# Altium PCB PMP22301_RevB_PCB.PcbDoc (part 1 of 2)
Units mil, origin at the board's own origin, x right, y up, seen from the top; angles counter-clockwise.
Board outline 2805 x 3100 mil, 4 copper layers (Top Layer, Signal Layer 1, Signal Layer 2, Bottom Layer), stack 61.2 mil thick; 104 components, 74 nets, 288 pads, 112 vias.
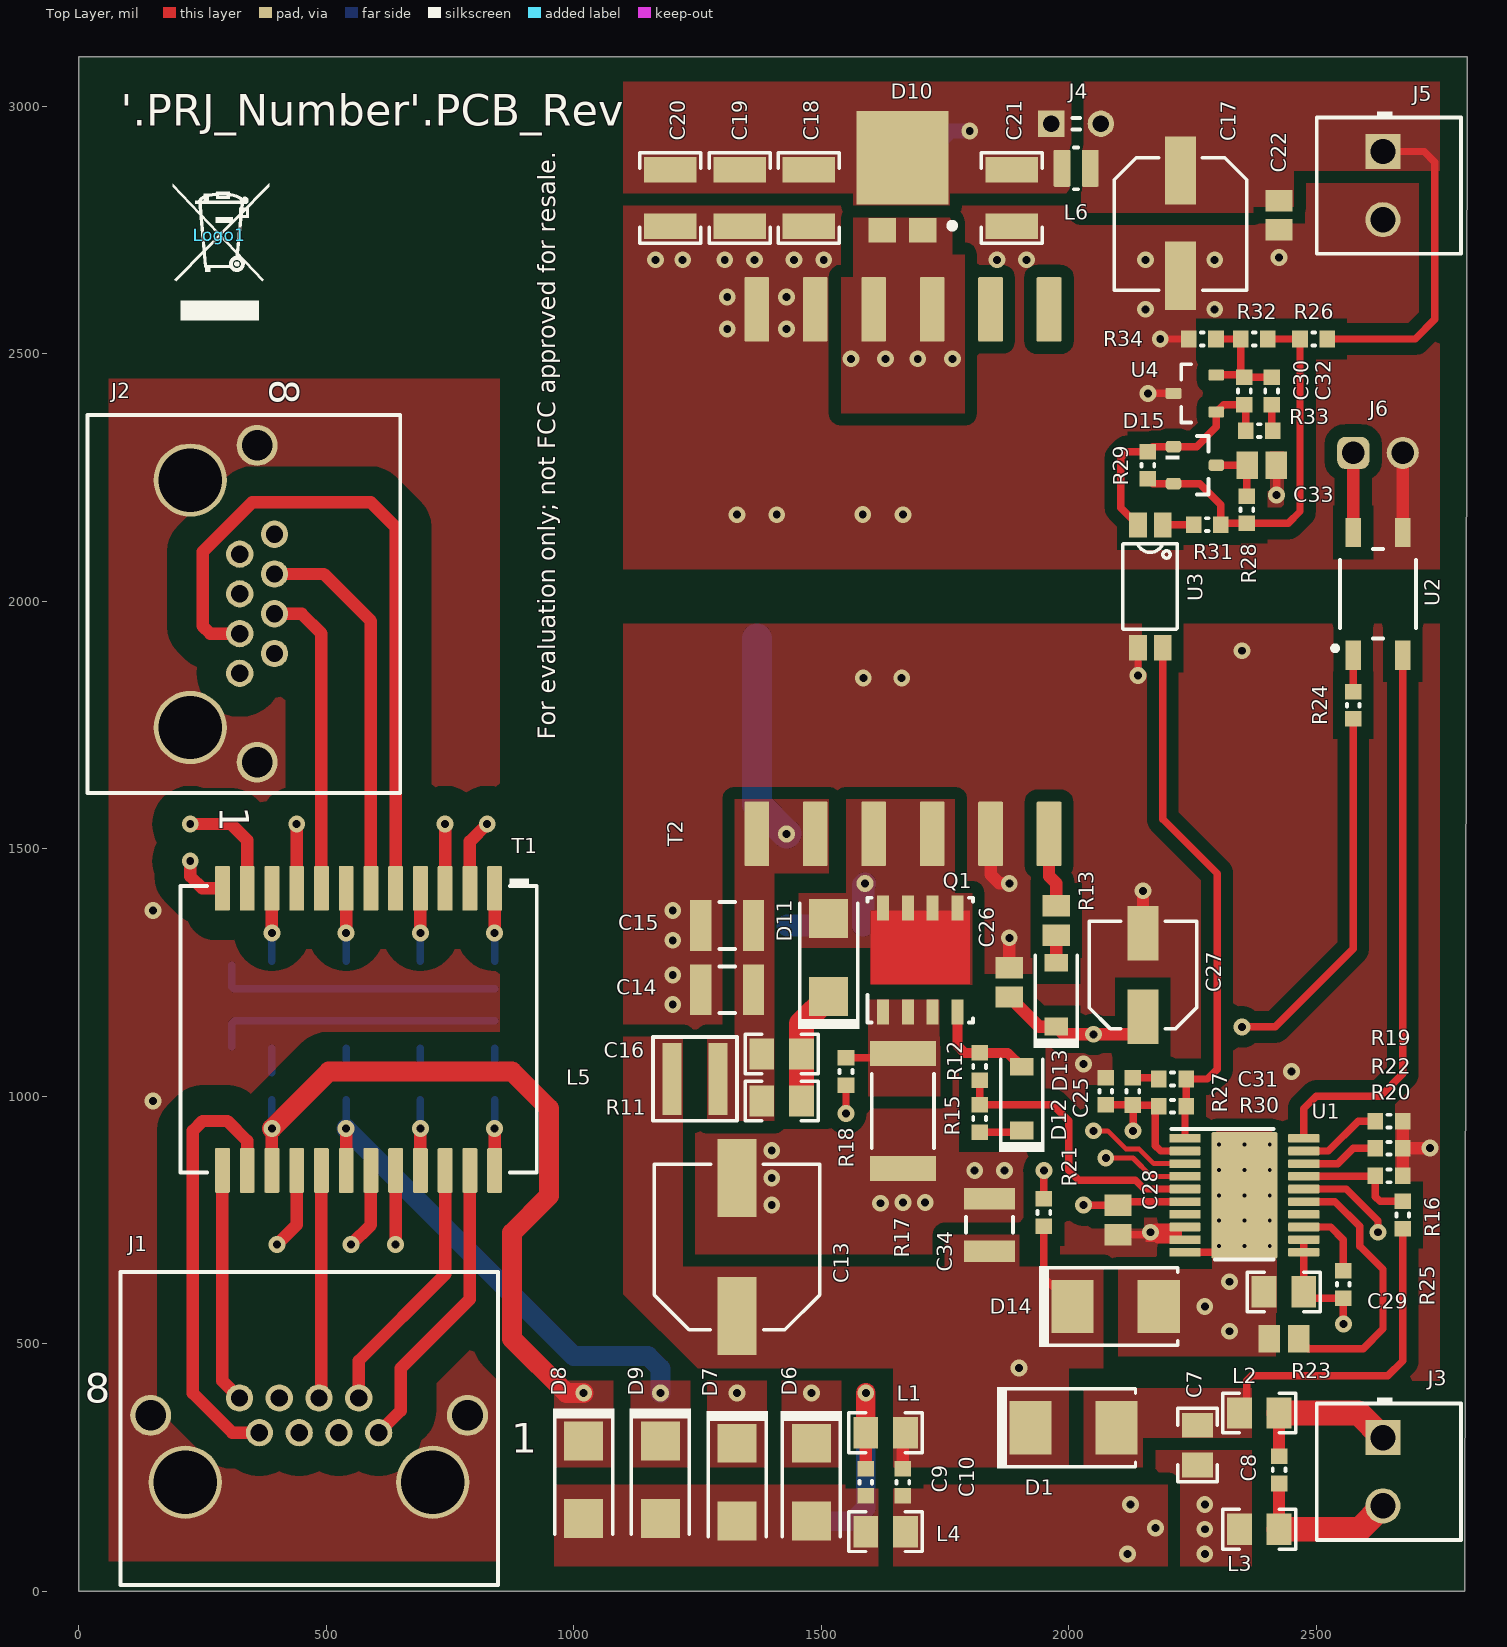
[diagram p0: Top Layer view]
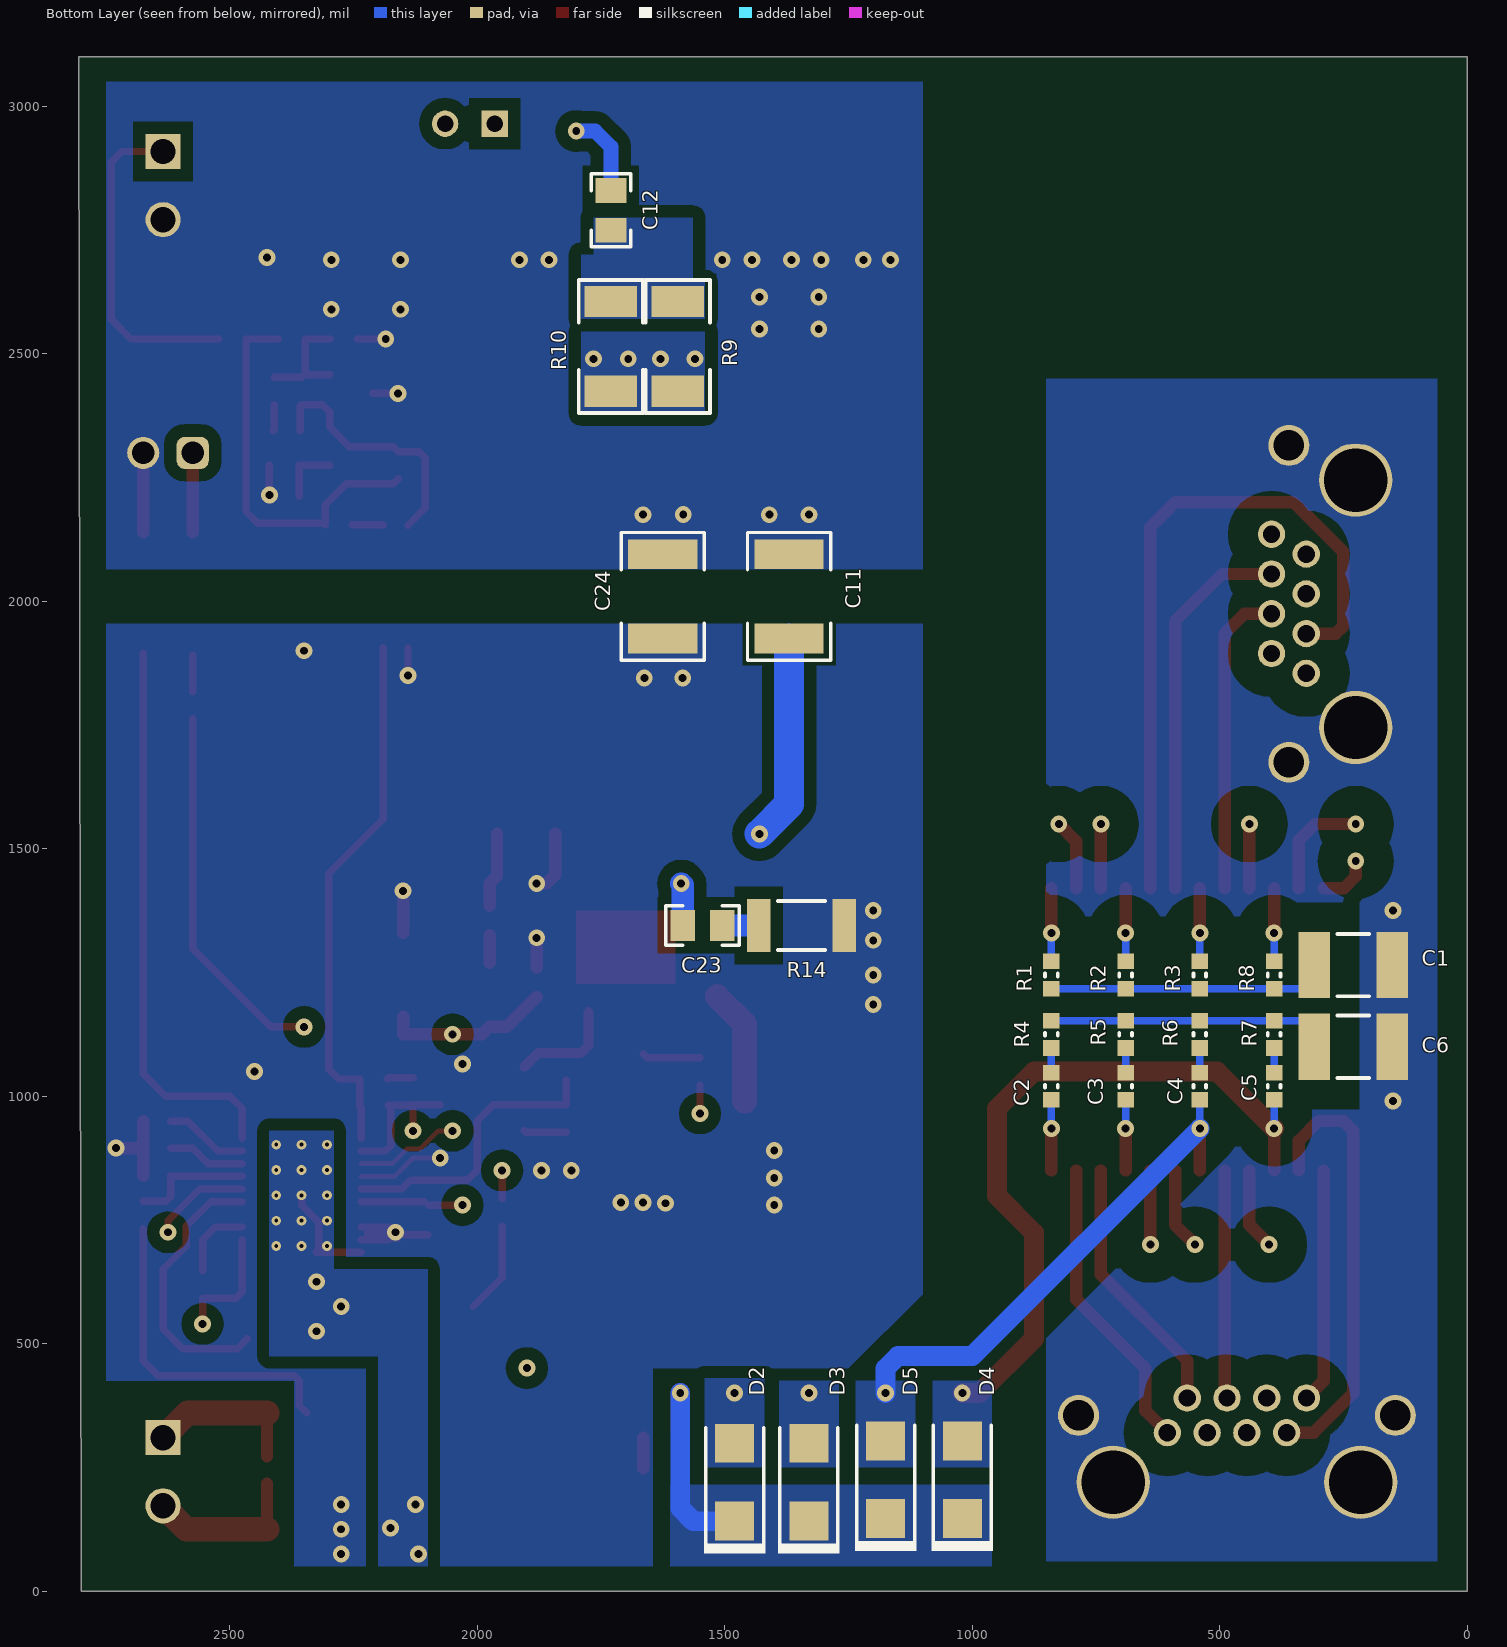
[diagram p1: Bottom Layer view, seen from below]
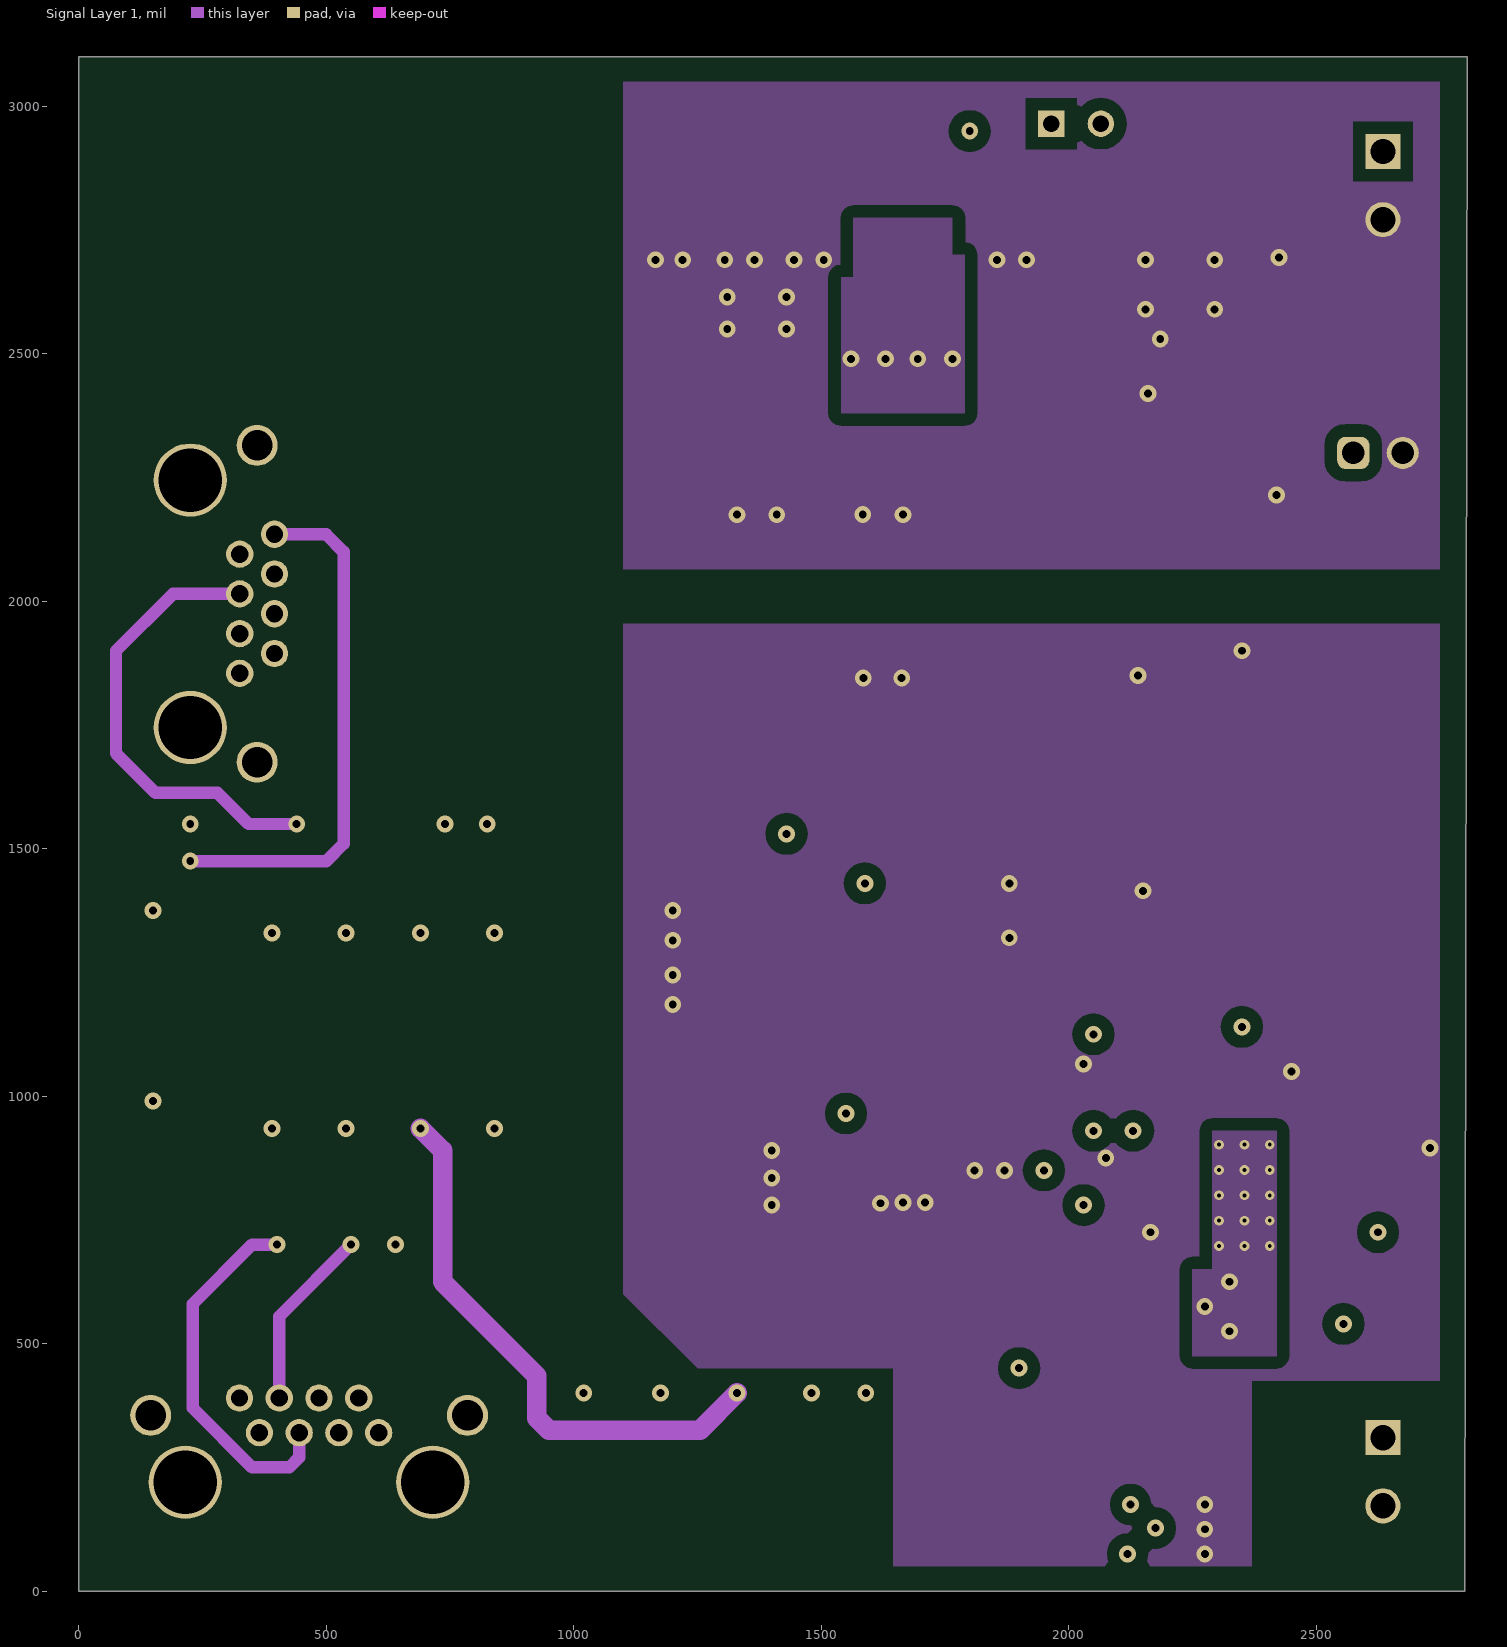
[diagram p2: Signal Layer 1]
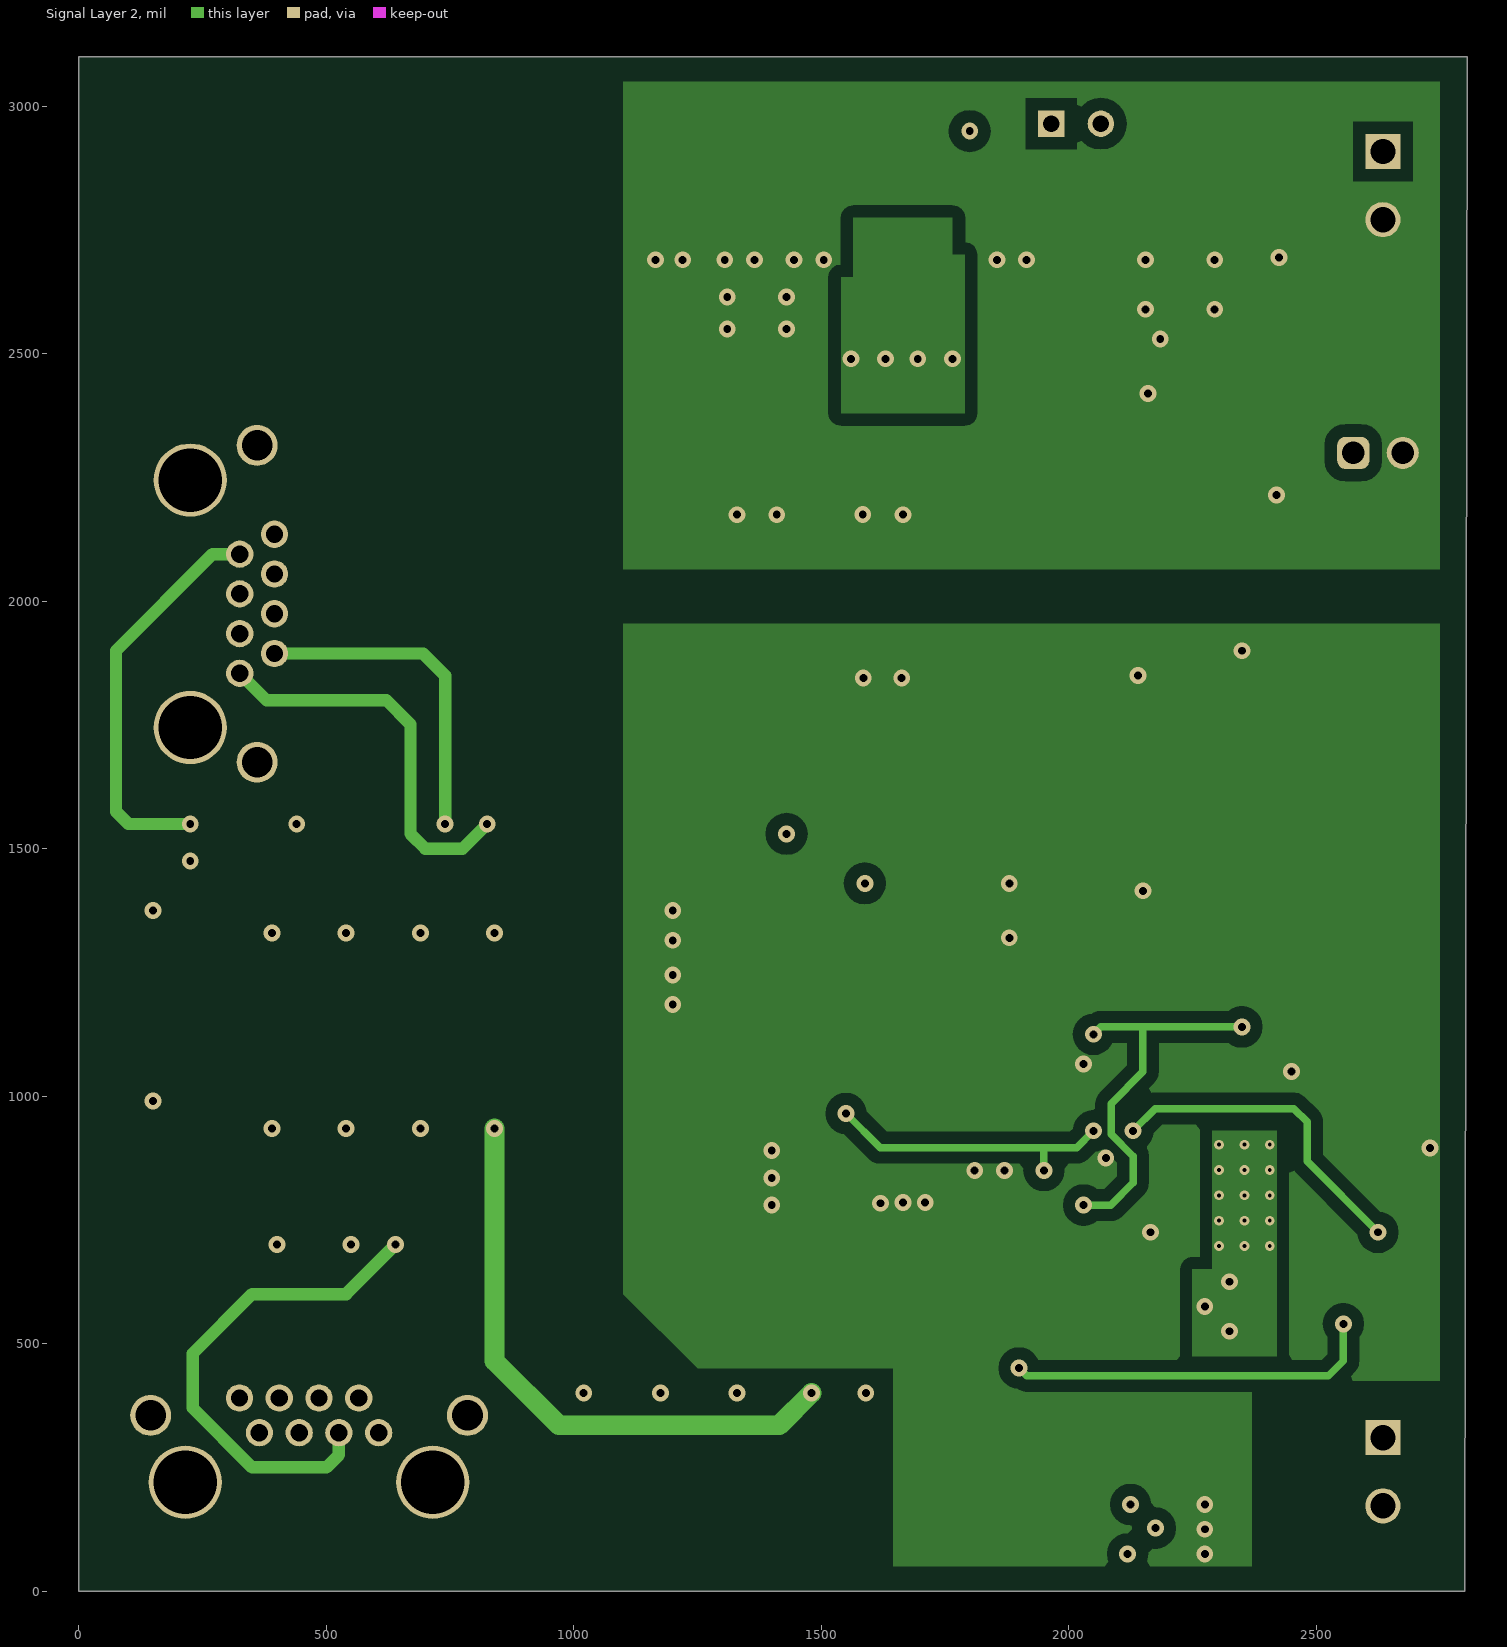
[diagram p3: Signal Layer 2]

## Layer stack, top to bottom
Top Solder: solder mask 0.4, Solder Resist, Dk 3.5
Top Layer: signal copper 2.8
Dielectric 2: core 15, Dk 4.2
Signal Layer 1: signal copper 2.8
Dielectric 3: prepreg 20, Dk 4.2
Signal Layer 2: signal copper 2.8
Dielectric1: core 15, FR-4, Dk 4.8
Bottom Layer: signal copper 2.8
Bottom Solder: solder mask 0.4, Solder Resist, Dk 3.5

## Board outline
0,0 2800,0 2805,3100 0,3100

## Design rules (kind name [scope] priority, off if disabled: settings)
AcuteAngle [All] p1: minimum=4.50000000000000E+0001 checktracksonly=FALSE
AssemblyTestPointUsage [All] p1: valid=2
BoardOutlineClearance BoardOutlineClearance_MountingHoles [OnCopper and InComponentClass('Mounting Holes')] p1: gap=39.37 ignorepadtopadclearanceinfootprint=FALSE
BoardOutlineClearance BoardOutlineClearance_Poly [OnCopper and IsPoly] p2: gap=25 ignorepadtopadclearanceinfootprint=FALSE
BoardOutlineClearance [OnCopper and Not InComponentClass('Logo') and not InComponentClass('FiducialMark') and not InRegion(1000,500,4000,800) and not InPoly] p3: gap=50 ignorepadtopadclearanceinfootprint=FALSE
Clearance Clearance_2 [InNamedPolygon('TOP_LAYER_BSP_P114')] p1: gap=60 ignorepadtopadclearanceinfootprint=FALSE
Clearance Clearance_1 [InNamedPolygon('BOTTOM_LAYER_BSP_P116')] p2: gap=60 ignorepadtopadclearanceinfootprint=FALSE
Clearance Clearance_Keepouts [((IsTrack Or IsArc) And Not InPoly) And IsFree and IsKeepOut vs ((IsTrack Or IsArc) And Not InPoly) And IsFree and IsKeepOut] p3: gap=0 ignorepadtopadclearanceinfootprint=FALSE
Clearance Clearance_Poly [InPolygon] p4: gap=25 ignorepadtopadclearanceinfootprint=TRUE
Clearance Clearance_FiducialMark [IsKeepOut and InComponentClass('FiducialMark') vs IsPad and InComponentClass('FiducialMark')] p5: gap=0 ignorepadtopadclearanceinfootprint=FALSE
Clearance [All] p6: gap=7.87 ignorepadtopadclearanceinfootprint=TRUE
ComponentClearance ComponentClearance_MountingHoles_FiducialMarks [InComponentClass('Mounting Holes') vs InComponentClass('FiducialMark')] p1: gap=50 collisioncheckmode=3 verticalgap=10 showdistances=FALSE
ComponentClearance ComponentClearance_Shunt [InComponentClass('Header') vs InComponentClass('Shunt')] p2: gap=0 collisioncheckmode=3 verticalgap=0 showdistances=FALSE
ComponentClearance ComponentClearance_Logo [InComponentClass('Logo')] p3: gap=50 collisioncheckmode=3 verticalgap=10 showdistances=FALSE
ComponentClearance ComponentClearance_ScrewToNut [(HasFootprint('NY PMS 440 0025 PH')) vs (HasFootprint('Keystone_1902C'))] p4: gap=5 collisioncheckmode=3 verticalgap=10 showdistances=FALSE
ComponentClearance ComponentClearance_MountingHoles [InComponentClass('Mounting Holes')] p5: gap=250 collisioncheckmode=3 verticalgap=100000 showdistances=FALSE
ComponentClearance ComponentClearance_SmallPassives [HasFootprint('0201*') or HasFootprint('0402*') or HasFootprint('0508') or HasFootprint('0603*') or HasFootprint('0612') or HasFootprint('0805*') or HasFootprint('0815*') or HasFootprint('0830*') or HasFootprint('1206*') or HasFootprint('1210*') or HasFootprint('1808*') or HasFootprint('1812*') or HasFootprint('1825*') or HasFootprint('2010*') or HasFootprint('2220*') or HasFootprint('2225*') or HasFootprint('2512*') or HasFootprint('2728*') or HasFootprint('3518*') vs HasFootprint('0201*') or HasFootprint('0402*') or HasFootprint('0508') or HasFootprint('0603*') or HasFootprint('0612') or HasFootprint('0805*') or HasFootprint('0815*') or HasFootprint('0830*') or HasFootprint('1206*') or HasFootprint('1210*') or HasFootprint('1808*') or HasFootprint('1812*') or HasFootprint('1825*') or HasFootprint('2010*') or HasFootprint('2220*') or HasFootprint('2225*') or HasFootprint('2512*') or HasFootprint('2728*') or HasFootprint('3518*')] p6: gap=14.96 collisioncheckmode=3 verticalgap=10 showdistances=FALSE
ComponentClearance ComponentClearance_THtoSMT [IsThruComponent vs IsSMTComponent] p7: gap=40 collisioncheckmode=3 verticalgap=30 showdistances=FALSE
ComponentClearance ComponentClearance_THtoTH [IsThruComponent vs IsThruComponent] p8: gap=30 collisioncheckmode=3 verticalgap=30 showdistances=FALSE
ComponentClearance [All] p9: gap=30 collisioncheckmode=3 verticalgap=10 showdistances=FALSE
DiffPairsRouting [All] p1: maxlimit=100 minlimit=10 mostfreqgap=10 toplayer_minwidth=15 toplayer_maxwidth=15 toplayer_prefwidth=15 midlayer1_minwidth=15 midlayer1_maxwidth=15 midlayer1_prefwidth=15 midlayer2_minwidth=15 midlayer2_maxwidth=15 midlayer2_prefwidth=15 bottomlayer_minwidth=15 bottomlayer_maxwidth=15 bottomlayer_prefwidth=15 maxuncoupledlength=1000
FabricationTestPointUsage TestPointUsage [All] p1: valid=2 allowmultiple=FALSE
FabricationTestpoint Testpoint [All] p1: side=3 testpointundercomponent=TRUE minsize=40 maxsize=100 preferedsize=60 minholesize=0 maxholesize=40 preferedholesize=32 testpointgrid=1 allowsidetop=TRUE allowsidebottom=TRUE usegrid=TRUE gridtolerance=0.01
FanoutControl Fanout_LCC [IsLCC] p1: bgadir=Out bgaviamode=Centered fanoutstyle=Auto fanoutdirection=Alternating viagrid=1 // Fanout_LCC (Default Rule)
FanoutControl Fanout_BGA [IsBGA] p2: bgadir=Out bgaviamode=Centered fanoutstyle=Auto fanoutdirection=Alternating viagrid=1 // Fanout_BGA (Default Rule)
FanoutControl Fanout_Default [All] p4: bgadir=Out bgaviamode=Centered fanoutstyle=Auto fanoutdirection=Alternating viagrid=1 // Fanout_Default (Default Rule)
FanoutControl Fanout_Small [(CompPinCount < 5)] p5: bgadir=Out bgaviamode=Centered fanoutstyle=Auto fanoutdirection=OutThenIn viagrid=1 // Fanout_Small (Default Rule)
HoleSize [All] p1: absolutevalues=TRUE maxlimit=251 minlimit=7.87 maxpercent=80.000 minpercent=20.000
MinimumAnnularRing MinimumAnnularRing_ThermalPadVias [IsVia and InAnyComponent] p1: minimumring=5.91
MinimumAnnularRing [All] p2: minimumring=7.87
MinimumSolderMaskSliver MinimumSolderMaskSliver_Logo [InComponentClass('Logo') vs InComponentClass('Logo')] p1: minsoldermaskwidth=0.7
MinimumSolderMaskSliver [All] p2: minsoldermaskwidth=3.94
PlaneConnect [All] p1: planeconnectstyle=Relief reliefexpansion=10 reliefentries=4 reliefconductorwidth=10 reliefairgap=10
PolygonConnect [All] p1: connectstyle=Direct reliefconductorwidth=10 reliefentries=4 polygonreliefangle="90 Angle" airgapwidth=10
RoutingVias ThermalPadVias [IsVia and InAnyComponent] p1: holewidth=7.87 width=19.68 viastyle="Through Hole" minholewidth=7.87 minwidth=19.68 maxholewidth=12.99 maxwidth=23.62
RoutingVias [All] p2: holewidth=16 width=34 viastyle="Through Hole" minholewidth=7.87 minwidth=26 maxholewidth=40 maxwidth=65
SilkToBoardRegionClearance [Not ((IsComment or IsDesignator) And (Hide <> 'False')) and not InRegion(1000,500,4000,800)] p1:
SilkToSilkClearance SilkToSilkClearance_Pb-FreeLogo [(HasFootprint('Pb-Free_Overlay_Medium') OR HasFootprint('Pb-Free_Overlay_Small')) vs (HasFootprint('Pb-Free_Overlay_Medium') OR HasFootprint('Pb-Free_Overlay_Small'))] p1: silktosilkclearance=0
SilkToSilkClearance [All] p2: silktosilkclearance=3.94
SilkToSolderMaskClearance SilkToComponentPadClearance [(IsPad or IsFill or IsRegion) and InAnycomponent] p1: minsilkscreentomaskgap=5 clearancetoexposedcopper=TRUE
SilkToSolderMaskClearance "Silk to Solder Mask Opening" [All] p2: minsilkscreentomaskgap=3.94 clearancetoexposedcopper=FALSE
SolderMaskExpansion [All] p1: expansion=1.97
UnRoutedNet [All] p1: checkbadconnections=TRUE
Width [All] p1: maxlimit=100 minlimit=6 preferedwidth=10 checkconnectedcopper=TRUE
14 further rules are at their usual default settings.

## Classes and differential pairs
component class PMP22301_RevB_SH2: C11 C12 C13 C14 C15 C16 C17 C18 C19 C20 C21 C22 C23 C24 C25 C26 C27 C28 C29 C30 C31 C32 C33 C34 D10 D11 D12 D13 D14 D15 J4 J5 J6 L5 L6 Q1 R9 R10 R11 R12 R13 R14 R15 R16 R17 R18 R19 R20 R21 R22 R23 R24 R25 R26 R27 R28 R29 R30 R31 R32 R33 R34 T2 U1 U2 U3 U4
component class PMP22301_RevB_SH1: C1 C2 C3 C4 C5 C6 C7 C8 C9 C10 D1 D2 D3 D4 D5 D6 D7 D8 D9 J1 J2 J3 L1 L2 L3 L4 Logo1 Logo2 R1 R2 R3 R4 R5 R6 R7 R8 T1
component class Header: J6

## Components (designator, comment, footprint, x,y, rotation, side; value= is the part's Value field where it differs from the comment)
C1 "GR443QR73D102KW01L" 1812 230,1265 r0 bottom value=1000pF
C2 "885012206114" 0603L 840,1020 r270 bottom value=0.01uF
C3 "885012206114" 0603L 690,1020 r270 bottom value=0.01uF
C4 "885012206114" 0603L 540,1020 r270 bottom value=0.01uF
C5 "885012206114" 0603L 390,1020 r270 bottom value=0.01uF
C6 "GR443QR73D102KW01L" 1812 230,1100 r180 bottom value=1000pF
C7 "885012207128" 0805_HV 2260,295 r90 top value=0.1uF
C8 "Capacitor" 0603L 2425,245 r270 top value=1000pF
C9 "Capacitor" 0603L 1590,220 r270 top value=1000pF
C10 "Capacitor" 0603L 1665,220 r270 top value=1000pF
C11 "Capacitor" 1812_HV 1370,2010 r270 bottom value=2200pF
C12 "GRM21A5C2E331JW01D" 0805_HV 1730,2790 r270 bottom value=330pF
C13 "Cap_Polarized" SM_RADIAL_F 1329.65,695.24 r90 top value=47uF
C14 "Capacitor" 1210_270L 1310,1215 r180 top value=2.2uF
C15 "Capacitor" 1210_270L 1310,1345 r180 top value=2.2uF
C16 "885012207128" 0805_HV 1420,1085 r180 top value=0.1uF
C17 "35SVPF22M" CAPSMT_62_F61 2225,2765 r270 top value=22uF
C18 "GRM32ER71H475KA88L" 1210_270 1475,2815 r90 top value=4.7uF
C19 "GRM32ER71H475KA88L" 1210_270 1335,2815 r90 top value=4.7uF
C20 "GRM32ER71H475KA88L" 1210_270 1195,2815 r90 top value=4.7uF
C21 "GRM32ER71H475KA88L" 1210_270 1885,2815 r90 top value=4.7uF
C22 "885012207103" 0805L 2425,2780 r270 top value=1uF
C23 "Capacitor" 0805_HV 1545,1345 r180 bottom value=100pF
C24 "Capacitor" 1812_HV 1625,2010 r270 bottom value=2200pF
C25 "Capacitor" 0603L 2075,1010 r270 top value=0.1uF
C26 "885012207103" 0805L 1880,1230 r90 top value=1uF
C27 "Cap_Polarized" SM_RADIAL_C 2150,1245 r90 top value=22uF
C28 "885012207103" 0805L 2099.69,749.68 r270 top value=1uF
C29 "885012207128" 0805_HV 2434.69,604.68 r0 top value=0.1uF
C30 "Capacitor" 0603L 2355,2425 r270 top value=100pF
C31 "GRM188R71E473KA01D" 0603L 2209.69,1034.68 r180 top value=0.047uF
C32 "GRM188R71E273KA01D" 0603L 2410,2425 r270 top value=0.027uF
C33 "885012207103" 0805L 2390,2275 r0 top value=1uF
C34 "Capacitor" 1210_270L 1840,740 r90 top value=2.2uF
D1 "B2100-13-F" SMB 2010,330 r0 top value=100V
D2 "B1100-13-F" SMA 1480,220 r90 bottom value=100V
D3 "B1100-13-F" SMA 1330,220 r90 bottom value=100V
D4 "B1100-13-F" SMA 1020,225 r90 bottom value=100V
D5 "B1100-13-F" SMA 1175,225 r90 bottom value=100V
D6 "B1100-13-F" SMA 1480,220 r270 top value=100V
D7 "B1100-13-F" SMA 1330,220 r270 top value=100V
D8 "B1100-13-F" SMA 1020,225 r270 top value=100V
D9 "B1100-13-F" SMA 1175,225 r270 top value=100V
D10 "FSV10150V" TO-277A 1664.06,2822.05 r180 top value=150V
D11 "ES1D-13-F" SMA 1515,1280 r90 top value=200V
D12 "MMSD4148T1G" SOD-123 1905,995 r90 top value=100V
D13 "MMSD4148T1G" SOD-123 1975,1205 r90 top value=100V
D14 "SMBJ58A-13-F" SMB 2095,575 r0 top value=58V
D15 "BAT54S-7-F" SOT-23L 2255,2275 r0 top value=30V
J1 "1-406541-1" TEC_1-406541-1 465.47,327.09 r0 top
J2 "1-406541-1" TEC_1-406541-1 332.09,1994.53 r270 top
J3 "691214110002" Wurth_691214110002 2635,241.1 r270 top
J4 "999-11-110-10-000000" Mill-Max_999-11-110-10-000000 2015,2965 r0 top
J5 "691214110002" Wurth_691214110002 2635,2840 r270 top
J6 "61300211121" WURTH_61300211121 2625,2300 r0 top
L1 "742792040" 0805_HV 1630,320 r0 top value="600 ohm"
L2 "742792040" 0805_HV 2385,360 r0 top value="600 ohm"
L3 "742792040" 0805_HV 2385,125 r0 top value="600 ohm"
L4 "742792040" 0805_HV 1630,120 r0 top value="600 ohm"
L5 "74438356022" WE-MAPI_4020 1245,1035 r0 top value=2.2uH
L6 "744383430033" WE-MAPI_2010 2015,2875 r0 top value=330nH
Logo1 "WEEE logo" WEEE_Minimum 285,2740 r0 top
Logo2 "FCC disclaimer" FCC_disclaimer 5777.56,383.86 r0 top
Q1 "FDMS86252" TRANS_Fairchild_PQFN08A 1700,1275 r90 top value=150V
R1 "Resistor" 0603L 840,1245 r270 bottom value=75.0
R2 "Resistor" 0603L 690,1245 r270 bottom value=75.0
R3 "Resistor" 0603L 540,1245 r270 bottom value=75.0
R4 "Resistor" 0603L 840,1125 r270 bottom value=75.0
R5 "Resistor" 0603L 690,1125 r270 bottom value=75.0
R6 "Resistor" 0603L 540,1125 r270 bottom value=75.0
R7 "Resistor" 0603L 390,1125 r270 bottom value=75.0
R8 "Resistor" 0603L 390,1245 r90 bottom value=75.0
R9 "CRCW2010100RJNEF" 2010 1595,2515 r90 bottom value=100
R10 "CRCW2010100RJNEF" 2010 1730,2515 r90 bottom value=100
R11 "CRCW080539K0JNEA" 0805_HV 1420,990 r180 top value=39k
R12 "CRCW0603100RJNEA" 0603L 1820,1060 r90 top value=100
R13 "CRCW080520R0JNEA" 0805L 1975,1355 r270 top value=20
R14 "Resistor" 2010L 1345,1345 r0 bottom value=75
R15 "Resistor" 0603L 1820,955 r270 top value=4.7
R16 "CRCW0603301KFKEA" 0603L 2675,760 r270 top value=301k
R17 "ERJ-L1WKF10CU" 2512 1665,970 r270 top value=0.1
R18 "CRCW06031K00FKEA" 0603L 1550,1050 r90 top value=1.00k
R19 "Resistor" 0603L 2647.13,949.68 r0 top value=69.8k
R20 "CRCW060328K0FKEA" 0603L 2647.13,838.86 r0 top value=28.0k
R21 "CRCW0603274KFKEA" 0603L 1950,765 r270 top value=274k
R22 "CRCW060349K9FKEA" 0603L 2647.13,894.68 r180 top value=49.9k
R23 "Resistor" 0805L 2435,510 r180 top value=63.4
R24 "CRCW060310K0FKEA" 0603L 2575,1790 r270 top value=10.0k
R25 "Resistor" 0603L 2554.69,619.68 r270 top value=24.9k
R26 "Resistor" 0603L 2495,2530 r0 top value=0
R27 "CRCW06031K50FKEA" 0603L 2129.69,1009.68 r90 top value=1.50k
R28 "Resistor" 0603L 2360,2185 r270 top value=10.0k
R29 "CRCW06036K04FKEA" 0603L 2160,2275 r90 top value=6.04k
R30 "Resistor" 0603L 2209.69,979.68 r180 top value=2.00k
R31 "CRCW06034K99FKEA" 0603L 2280,2155 r0 top value=4.99k
R32 "CRCW060310K0FKEA" 0603L 2375,2530 r0 top value=10.0k
R33 "CRCW060310K0FKEA" 0603L 2385,2345 r180 top value=10.0k
R34 "CRCW06031K15FKEA" 0603L 2270,2530 r180 top value=1.15k
T1 "7490220121" Wurth_7490220121 565,1135 r270 top value=350uH
T2 "PA6399-AL" FP-PA6399-AL_SMT_TRANSFORMER_20MM57_20MM57-MFG 1665,2060 r90 top
U1 "TPS23754PWP" PWP0020D_M 2355,799.68 r0 top
U2 "PC357N4J000F" BESOP-4 2625,2015 r90 top
U3 "TCMT1107" SOP-4 2165,2030 r270 top
U4 "TL431LIAIDBZR" DBZ0003A_L 2255,2420 r180 top

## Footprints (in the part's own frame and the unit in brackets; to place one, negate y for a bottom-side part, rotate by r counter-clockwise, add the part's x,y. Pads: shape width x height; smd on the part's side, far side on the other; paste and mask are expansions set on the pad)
0603L [mm] "0603 from SM-752 data"
  rect 0.8x0.85 smd: 1(-0.7,0) 2(0.7,0)
  silkscreen extent -0.07,-0.33 0.07,0.33, body extent -0.87,-0.47 0.87,0.47, height 1
0805_HV [mil] "0805 with 30mil clearance between pads"
  rect 50x63 smd: 1(-40,0) 2(40,0)
  silkscreen extent -74,-40 74,40, body extent -43,-29 43,29, height 57
0805L [mm] "0805 from SM-752 data"
  rect 1.1x1.4 smd: 1(-0.75,0) 2(0.75,0)
  body extent -1.1,-0.72 1.1,0.72, height 1.45
1210_270 [mm] "1210"
  rect 1.3x2.7 smd: 1(-1.45,0) 2(1.45,0)
  silkscreen extent -2.32,-1.57 2.32,1.57, body extent -1.7,-1.35 1.7,1.35, height 2.7
1210_270L [mm] "1210"
  rect 1.1x2.6 smd: 1(-1.35,0) 2(1.35,0)
  silkscreen extent -0.4,-1.2 0.4,1.2, body extent -1.7,-1.35 1.7,1.35, height 2.7
1812 [mm]
  rect 1.6x3.4 smd: 1(-2,0) 2(2,0)
  silkscreen extent -0.8,-1.6 0.8,1.6, body extent -2.4,-1.7 2.4,1.7, height 1.35
1812_HV [mil] "PRG recommended land pattern"
  rect 60x140 smd: 1(-85,0) 2(85,0)
  silkscreen extent -129,-84 129,84, body extent -94,-67 94,67, height 53
2010 [mm] "Chip Capacitor, Body 5.08x2.54mm, IPC Medium Density"
  rect 1.6x2.7 smd: 1(-2.3,0) 2(2.3,0)
  silkscreen extent -3.42,-1.65 3.42,1.65, body extent -2.73,-1.45 2.73,1.45, height 1.66
2010L [mm]
  rect 1.2x2.7 smd: 1(-2.2,0) 2(2.2,0)
  silkscreen extent -1.2,-1.25 1.2,1.25, body extent -2.73,-1.45 2.73,1.45, height 1.66
2512 [mm] "Chip Resistor, Body 6.3x3.2mm, IPC Medium Density"
  rect 1.3x3.4 smd: 1(-2.95,0) 2(2.95,0)
  silkscreen extent -1.9,-1.6 1.9,1.6, body extent -3.22,-1.67 3.22,1.67, height 0.71
BESOP-4 [mm] "Sharp"
  rect 1.5x0.8 smd: 1(-3.15,1.27) 2(-3.15,-1.27) 3(3.15,-1.27) 4(3.15,1.27)
  silkscreen extent -2.92,-1.95 2.3,2.33, body extent -3.6,-1.95 3.6,1.95, height 2.91
CAPSMT_62_F61 [mm] "6.3 x 5.8mm:  Chemi-Con F61"
  rect 3.5x1.6 smd: 1(-2.675,0.025) 2(2.725,0.025)
  silkscreen extent -3.34,-3.38 3.46,3.42, body extent -3.37,-3.38 3.46,3.43, height 6.1
DBZ0003A_L [mm] "SOT23, 3-Leads, Body 2.9x1.3mm, Pitch 0.95mm, Lead Span 2.4mm, IPC High Density"
  rrect18% 0.8x0.55 smd: 1(-1.1,0.95) 2(-1.1,-0.95) 3(1.1,0)
  silkscreen extent 0.2,-1.5 0.7,1.5, body extent -1.26,-1.46 1.26,1.46, height 0.98
FCC_disclaimer [mil]
FP-PA6399-AL_SMT_TRANSFORMER_20MM57_20MM57-MFG [mm]
  rrect8% 3.3x1.27 smd paste+0 mask+0: 1(-13.46,7.5) 2(-13.46,4.5) 3(-13.46,1.5) 4(-13.46,-1.5) 5(-13.46,-4.5) 6(-13.46,-7.5) 7(13.46,-7.5) 8(13.46,-4.5) 9(13.46,-1.5) 10(13.46,1.5) 11(13.46,4.5) 12(13.46,7.5)
  body extent -15.21,-10.39 15.21,10.39, height 0.25
Mill-Max_999-11-110-10-000000 [mm] "Shorting Jumper, 2.54mm, 2 Position, Gold, TH"
  rect 1.35x1.35 hole 0.85: 1(-1.27,0)
  round 1.35 hole 0.85: 2(1.27,0)
  silkscreen extent -0.2,-0.3 0.2,0.3, body extent -1.55,-0.28 1.55,0.28, height 1.9
PWP0020D_M [mm] "HTSSOP-20, IPC Low Density"
  rrect22% 1.6x0.45 smd: 1(-3.05,2.925) 2(-3.05,2.275) 3(-3.05,1.625) 4(-3.05,0.975) 5(-3.05,0.325) 6(-3.05,-0.325) 7(-3.05,-0.975) 8(-3.05,-1.625) 9(-3.05,-2.275) 10(-3.05,-2.925) 11(3.05,-2.925) 12(3.05,-2.275) 13(3.05,-1.625) 14(3.05,-0.975) 15(3.05,-0.325) 16(3.05,0.325) 17(3.05,0.975) 18(3.05,1.625) 19(3.05,2.275) 20(3.05,2.925)
  rrect6% 3.4x6.5 smd paste-2 mask-2: 21(0,0)
  silkscreen extent -3.75,-3.3 1.5,3.4, body extent -3.2,-3.25 3.2,3.25, height 1.13
SM_RADIAL_C [mm] "5 x 5.8mm:  Panasonic C"
  rect 2.8x1.6 smd: 1(-2.15,0) 2(2.15,0)
  silkscreen extent -2.75,-2.75 2.75,2.75, body extent -2.75,-2.75 2.75,2.75, height 6.1
SM_RADIAL_F [mm] "8 x 10.2mm:  Panasonic F"
  rect 4x2 smd: 1(-3.55,0) 2(3.55,0)
  silkscreen extent -4.25,-4.25 4.25,4.25, body extent -4.25,-4.25 4.25,4.25, height 10.5
SMA [mm] "Molded Diode, 2-Leads, Body 4.3x2.6mm, IPC Medium Density, based on OnSemi component dimensions and land pattern"
  rect 2x2 smd: 1(-2,0) 2(2,0)
  silkscreen extent -3.66,-1.57 2.79,1.57, body extent -2.6,-1.3 2.6,1.3, height 2.42
SMB [mil] "Molded Diode, 2-Leads, Body 5.4x3.6mm, IPC Medium Density, based on OnSemi component dimensions"
  rect 85x107.99 smd: 1(-87.01,0) 2(87.01,0)
  silkscreen extent -155,-82 125,82, body extent -106,-71 106,71, height 91
SOD-123 [mm] "On Semi recommended land pattern"
  rect 0.915x1.22 smd: 1(-1.637,0) 2(1.637,0)
  silkscreen extent -2.74,-1.17 2.03,1.17, body extent -1.93,-0.9 1.93,0.9, height 1.35
SOP-4 [mm] "Vishay Half Pitch Mini-Flat Package"
  rect 1.3x0.9 smd: 1(-3.15,0.635) 2(-3.15,-0.635) 3(3.15,-0.635) 4(3.15,0.635)
  silkscreen extent -2.2,-1.41 2.2,1.39, body extent -3.5,-1.4 3.5,1.4, height 2.12
SOT-23L [mm] "SOT23, 3-Leads, Body 2.9x1.3mm, Pitch 0.95mm, Lead Span 2.5mm, IPC High Density"
  rrect50% 0.8x0.6 smd: 1(-1.1,0.95) 2(-1.1,-0.95) 3(1.1,0)
  silkscreen extent -1.5,-1.5 0.7,1.5, body extent -1.16,-1.45 1.21,1.45, height 1
TEC_1-406541-1 [mm] "TE Connectivity"
  round 1.4 hole 0.89: 1(3.56,-0.18) 2(2.54,1.6) 3(1.52,-0.18) 4(0.5,1.6) 5(-0.52,-0.18) 6(-1.54,1.6) 7(-2.56,-0.18) 8(-3.58,1.6)
  round 2.1 hole 1.57: 9(8.12,0.71) 10(-8.14,0.71)
  round 3.759 hole 3.251: 11(6.34,-2.72) 12(-6.36,-2.72)
  silkscreen extent -9.69,-8 9.69,8.06, body extent -9.33,-8 9.31,7.75, height 14.8
TO-277A [mm] "Vishay"
  rect 1.4x1.27 smd: 1(-1.04,1.83) 2(1.04,1.83)
  rect 4.72x4.8 smd: 3(0,-1.883)
  silkscreen extent -2.7,1.45 -2.4,1.75, body extent -2.35,-4.2 2.4,2.45, height 1.2
TRANS_Fairchild_PQFN08A [mm] "Fairchild PQFN08A recommended land pattern"
  rect 1.27x0.61 smd: 1(-2.67,1.905) 2(-2.67,0.635) 3(-2.67,-0.635) 4(-2.67,-1.905) 5(2.67,-1.905) 6(2.67,-0.635) 7(2.67,0.635) 8(2.67,1.905)
  Top Layer region: -1.215,-2.55 2.535,-2.55 2.535,2.55 -1.215,2.55
  silkscreen extent -3.2,-2.7 3.2,2.7, body extent -3.05,-2.55 3.05,2.55, height 1.11
WE-MAPI_2010 [mm] "WURTH"
  rrect12% 0.85x1.9 smd: 1(-0.725,0) 2(0.725,0)
  silkscreen extent -0.1,-1.07 0.1,1.07, body extent -1.1,-0.9 1.1,0.9, height 1
WE-MAPI_4020 [mm] "SMD, 2-Leads, Body 4.1x4.1mm"
  rect 0.98x3.7 smd: 1(-1.185,0) 2(1.185,0)
  silkscreen extent -2.15,-2.15 2.15,2.15, body extent -2.15,-2.15 2.15,2.15, height 2.1
WEEE_Minimum [mil] "WEEElie bin"
  silkscreen extent -95,-172 99,104
Wurth_7490220121 [mm] "SMT, 24-Leads, Body 14.7x18.29mm, Pitch 1.27mm"
  rrect13% 2.29x0.76 smd: 1(-7.24,6.985) 2(-7.24,5.715) 3(-7.24,4.445) 4(-7.24,3.175) 5(-7.24,1.905) 6(-7.24,0.635) 7(-7.24,-0.635) 8(-7.24,-1.905) 9(-7.24,-3.175) 10(-7.24,-4.445) 11(-7.24,-5.715) 12(-7.24,-6.985) 13(7.24,-6.985) 14(7.24,-5.715) 15(7.24,-4.445) 16(7.24,-3.175) 17(7.24,-1.905) 18(7.24,-0.635) 19(7.24,0.635) 20(7.24,1.905) 21(7.24,3.175) 22(7.24,4.445) 23(7.24,5.715) 24(7.24,6.985)
  silkscreen extent -7.75,-9.15 7.35,9.15, body extent -8,-9.14 8,9.15, height 6.15
WURTH_61300211121 [mm] "Header, 2.54mm, 2x1, TH"
  rrect50% 1.65x1.65 hole 1.15: 1(-1.27,0)
  round 1.65 hole 1.15: 2(1.27,0)
  body extent -2.54,-1.27 2.54,1.27, height 8.54
Wurth_691214110002 [mm] "Receptacle, 3.5mm, 2x1, TH"
  rect 1.8x1.8 hole 1.3: 1(-1.75,0)
  round 1.8 hole 1.3: 2(1.75,0)
  silkscreen extent -3.8,-3.4 3.5,4, body extent -3.9,-3.4 3.5,4, height 8.5

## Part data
C1 C6: library part CMP-0009438-2, "CAP, CERM, 1000 pF, 2000 V, +/- 10%, X7R, 1812", Cap_Case=1812, Manufacturer=MuRata, TempCo=X7R, Tolerance_%=10%, Value1=Unknown, Value2=2000V, ValueDisplayed=1000pF
C2 C3 C4 C5: library part CMP-0079993-1, "CAP, CERM, 0.01 µF, 100 V,+/- 10%, X7R, 0603", Cap_Case=0603, Manufacturer="Wurth Elektronik", Supplier Part Number 1=45AC8565, TempCo=X7R, Tolerance_%=10%, Value2=100V, ValueDisplayed=0.01µF
C7 C16 C29: library part CMP-0750058-1, "CAP, CERM, 0.1 µF, 100 V,+/- 10%, X7R, 0805", Cap_Case=0805, Manufacturer="Wurth Elektronik", TempCo=X7R, Tolerance_%=10%, Value2=100V, ValueDisplayed=0.1µF
C8 C9 C10: library part CMP-0007053-4, "CAP, CERM, 1000 pF, 100 V, +/- 10%, X7R, 0603", Cap_Case=0603, Manufacturer=TDK, PartNumber=C1608X7R2A102K080AA, Supplier Part Number 1=445-1298-1-ND, TempCo=X7R, Tolerance_%=10%, Value1=Unknown, Value2=100V, ValueDisplayed=1000pF
C11 C24: library part CMP-0009358-2, "CAP, CERM, 2200 pF, 2000 V, +/- 10%, X7R, 1812", Cap_Case=1812, Manufacturer=TDK, PartNumber=C4532X7R3D222K130KA, Supplier Part Number 1=445-2389-1-ND, TempCo=X7R, Tolerance_%=10%, Value1=Unknown, Value2=2000V, ValueDisplayed=2200pF
C12: library part CMP-0081666-1, "CAP, CERM, 330 pF, 250 V,+/- 5%, C0G/NP0, 0805", Cap_Case=0805, Manufacturer=MuRata, Supplier Part Number 1=490-14654-1-ND, TempCo=C0G/NP0, Tolerance_%=5%, Value2=250V, ValueDisplayed=330pF
C13: library part CMP-0011192-2, "CAP, AL, 47 uF, 63 V, +/- 20%, 0.65 ohm, AEC-Q200 Grade 2, SMD", Cap_Case=F, Manufacturer=Panasonic, PartNumber=EEE-FK1J470P, Supplier Part Number 1=PCE3823CT-ND, Tolerance_%=20%, Value1="0.65 ohm", Value2=63V, ValueDisplayed=47uF
C14 C15 C34: library part CMP-0009232-2, "CAP, CERM, 2.2 uF, 100 V, +/- 10%, X7R, 1210", Cap_Case=1210, Manufacturer=MuRata, PartNumber=GRM32ER72A225KA35L, Supplier Part Number 1=490-3385-1-ND, TempCo=X7R, Tolerance_%=10%, Value1="0.007 ohm", Value2=100V, ValueDisplayed=2.2uF
C17: library part CMP-0012134-3, "CAP, Aluminum Polymer, 22 uF, 35 V, +/- 20%, 0.035 ohm, F61 SMD", Manufacturer=Panasonic, Tolerance_%=20%, Value1="0.035 ohm", Value2=35V, ValueDisplayed=22uF
C18 C19 C20 C21: library part CMP-0009228-2, "CAP, CERM, 4.7 uF, 50 V, +/- 10%, X7R, 1210", Cap_Case=1210, Manufacturer=MuRata, Supplier Part Number 1=490-1864-1-ND, TempCo=X7R, Tolerance_%=10%, Value1="0.002 ohm", Value2=50V, ValueDisplayed=4.7uF
C22 C26 C28 C33: library part CMP-0007696-2, "CAP, CERM, 1 uF, 50 V, +/- 10%, X7R, 0805", Cap_Case=0805, Manufacturer="Wurth Elektronik", Supplier Part Number 1=710-885012207103, TempCo=X7R, Tolerance_%=10%, Value1=Unknown, Value2=50V, ValueDisplayed=1uF
C23: library part CMP-0008236-2, "CAP, CERM, 100 pF, 250 V, +/- 5%, C0G/NP0, 0805", Cap_Case=0805, Manufacturer=MuRata, PartNumber=GRM21A5C2E101JW01D, Supplier Part Number 1=490-5542-1-ND, TempCo=C0G/NP0, Tolerance_%=5%, Value1=Unknown, Value2=250V, ValueDisplayed=100pF
C25: library part CMP-0007039-5, "CAP, CERM, 0.1 uF, 25 V, +/- 10%, X7R, 0603", Cap_Case=0603, Manufacturer=TDK, PartNumber=C1608X7R1E104K080AA, Supplier Part Number 1=445-1316-1-ND, TempCo=X7R, Tolerance_%=10%, Value1=Unknown, Value2=25V, ValueDisplayed=0.1uF
C27: library part CMP-0010713-1, "CAP, AL, 22 uF, 25 V, +/- 20%, 0.7 ohm, AEC-Q200 Grade 2, SMD", Cap_Case=C, Manufacturer=Panasonic, PartNumber=EEE-FK1E220R, Supplier Part Number 1=PCE3799CT-ND, Tolerance_%=20%, Value1="0.7 ohm", Value2=25V, ValueDisplayed=22uF
C30: library part CMP-0007171-4, "CAP, CERM, 100 pF, 50 V, +/- 5%, C0G/NP0, 0603", Cap_Case=0603, Manufacturer=MuRata, PartNumber=GRM1885C1H101JA01D, Supplier Part Number 1=490-1427-1-ND, TempCo=C0G/NP0, Tolerance_%=5%, Value1=Unknown, Value2=50V, ValueDisplayed=100pF
C31: library part CMP-0007423-4, "CAP, CERM, 0.047 uF, 25 V, +/- 10%, X7R, 0603", Cap_Case=0603, Manufacturer=MuRata, Supplier Part Number 1=490-1522-1-ND, TempCo=X7R, Tolerance_%=10%, Value1=Unknown, Value2=25V, ValueDisplayed=0.047uF
C32: library part CMP-0007417-5, "CAP, CERM, 0.027 uF, 25 V, +/- 10%, X7R, 0603", Cap_Case=0603, Manufacturer=MuRata, Supplier Part Number 1=81-GRM188R71E273KA, TempCo=X7R, Tolerance_%=10%, Value1=Unknown, Value2=25V, ValueDisplayed=0.027uF
D1: library part CMP-0028397-2, "Diode, Schottky, 100 V, 2 A, SMB", Manufacturer="Diodes Inc.", Value1=2A, Value2=0.79V
D2 D3 D4 D5 D6 D7 D8 D9: library part CMP-0028371-2, "Diode, Schottky, 100 V, 1 A, SMA", Manufacturer="Diodes Inc.", Value1=1A, Value2=0.79V
D10: library part CMP-0028890-2, "Diode, Schottky, 150 V, 10 A, AEC-Q101, TO-277A", Manufacturer="Fairchild Semiconductor", Value1=10A, Value2=0.84V
D11: library part CMP-0029024-2, "Diode, Ultrafast, 200 V, 1 A, SMA", Manufacturer="Diodes Inc.", Value1=1A, Value2=0.92V
D12 D13: library part CMP-0029032-2, "Diode, Switching, 100 V, 0.2 A, SOD-123", Manufacturer="ON Semiconductor", Value1=0.2A, Value2=1V
D14: library part CMP-0005583-3, "Diode, TVS, Uni, 58 V, 93.6 Vc, SMB", Manufacturer="Diodes Inc.", Value1=600W
D15: library part CMP-0028456-2, "Diode, Schottky, 30 V, 0.2 A, SOT-23", Manufacturer="Diodes Inc.", Value1=0.2A, Value2=0.65V
J1 J2: library part CMP-0054918-1, "RJ45, No LED, tab up, R/A, TH", Color=Black, Manufacturer="TE Connectivity", Supplier Part Number 1=A97716-ND
J3 J5: library part CMP-0054825-2, "Terminal Block, 3.5mm, 2x1, Tin, TH", Color=Green, Current_A=10A, Manufacturer="Wurth Elektronik", Supplier Part Number 1=732-2747-ND, Voltage_V=300V
J4: library part CMP-0055047-1, "Shorting Jumper, 2.54mm, 2 Position, Gold, TH", Manufacturer=Mill-Max, Supplier Part Number 1=ED1332-ND
J6: library part CMP-0054794-2, "Header, 2.54 mm, 2x1, Gold, TH", Color=Black, Manufacturer="Wurth Elektronik", Supplier Part Number 1=732-5315-ND
L1 L2 L3 L4: library part CMP-0003084-1, "Ferrite Bead, 600 ohm @ 100 MHz, 2 A, 0805", Manufacturer="Wurth Elektronik", Supplier Part Number 1=732-1620-1-ND, Value1="0.15 ohm", Value2=2A, ValueDisplayed="600 ohm"
L5: library part CMP-0064169-1, "Inductor, Shielded, 3.3 uH, 3.6 A, 0.0399 ohm, SMD", Manufacturer="Wurth Elektronik", PartNumber=74438356033, Supplier Part Number 1=732-8232-1-ND, Value1="0.029 ohm", Value2=4.7A, ValueDisplayed=3.3uH
L6: library part CMP-0064158-1, "Inductor, Shielded, 330 nH, 2.5 A, 0.053 ohm, SMD", Manufacturer="Wurth Elektronik", Supplier Part Number 1=732-5701-1-ND, Value1="0.053 ohm", Value2=2.5A, ValueDisplayed=330nH
Logo1: library part CMP-0074769-1
Logo2: library part CMP-0074847-1, "FCC_disclaimer"
Q1: library part CMP-0001058-1, "MOSFET, N-CH, 150 V, 4.6 A, PQFN08A", Alternate Manufacturer=None, Manufacturer="Fairchild Semiconductor", Supplier Part Number 1=FDMS86252CT-ND, Value1=0, Value2="11 nC"
R1 R2 R3 R4 R5 R6 R7 R8: library part CMP-0022590-4, "RES, 75.0, 1%, 0.1 W, AEC-Q200 Grade 0, 0603", Manufacturer=Vishay-Dale, PartNumber=CRCW060375R0FKEA, Power_W=100mW, Supplier Part Number 1=541-75.0HCT-ND, TempCo="100 ppm/C", Tolerance_%=1%, Value2=0.1W, Value_Code=75R0, ValueDisplayed=75.0
R9 R10: library part CMP-0016046-3, "RES, 100, 5%, 0.75 W, AEC-Q200 Grade 0, 2010", Manufacturer=Vishay-Dale, Power_W=750mW, Supplier Part Number 1=541-100WCT-ND, TempCo="200 ppm/C", Tolerance_%=5%, Value2=0.75W, Value_Code=100R, ValueDisplayed=100
R11: library part CMP-0020536-3, "RES, 39 k, 5%, 0.125 W, AEC-Q200 Grade 0, 0805", Manufacturer=Vishay-Dale, Power_W=125mW, Supplier Part Number 1=541-39KACT-ND, TempCo="200 ppm/C", Tolerance_%=5%, Value2=0.125W, Value_Code=39k0, ValueDisplayed=39k
R12: library part CMP-0025700-4, "RES, 100, 5%, 0.1 W, AEC-Q200 Grade 0, 0603", Manufacturer=Vishay-Dale, Power_W=100mW, Supplier Part Number 1=541-100GCT-ND, TempCo="200 ppm/C", Tolerance_%=5%, Value2=0.1W, Value_Code=100R, ValueDisplayed=100
R13: library part CMP-0020497-3, "RES, 20, 5%, 0.125 W, AEC-Q200 Grade 0, 0805", Manufacturer=Vishay-Dale, Power_W=125mW, Supplier Part Number 1=541-20ACT-ND, TempCo="200 ppm/C", Tolerance_%=5%, Value2=0.125W, Value_Code=20R0, ValueDisplayed=20
R14: library part CMP-0016178-3, "RES, 75, 5%, 0.75 W, AEC-Q200 Grade 0, 2010", Manufacturer=Vishay-Dale, PartNumber=CRCW201075R0JNEF, Power_W=750mW, Supplier Part Number 1=541-75.0WCT-ND, TempCo="200 ppm/C", Tolerance_%=5%, Value2=0.75W, Value_Code=75R0, ValueDisplayed=75
R15: library part CMP-0025821-4, "RES, 4.7, 5%, 0.1 W, AEC-Q200 Grade 0, 0603", Manufacturer=Vishay-Dale, PartNumber=CRCW06034R70JNEA, Power_W=100mW, Supplier Part Number 1=541-4.7GCT-ND, TempCo="200 ppm/C", Tolerance_%=5%, Value2=0.1W, Value_Code=4R70, ValueDisplayed=4.7
R16: library part CMP-0022320-4, "RES, 301 k, 1%, 0.1 W, AEC-Q200 Grade 0, 0603", Manufacturer=Vishay-Dale, Power_W=100mW, Supplier Part Number 1=541-301KHCT-ND, TempCo="100 ppm/C", Tolerance_%=1%, Value2=0.1W, Value_Code=301k
R17: library part CMP-0015806-2, "RES, 0.12, 1%, 1 W, 2512", Manufacturer=Panasonic, PartNumber=ERJ-L1WKF12CU, Power_W=1W, Supplier Part Number 1=1577587, TempCo="100 ppm/C", Tolerance_%=1%, Value_Code=R100, ValueDisplayed=0.12
R18: library part CMP-0022109-5, "RES, 1.00 k, 1%, 0.1 W, AEC-Q200 Grade 0, 0603", Manufacturer=Vishay-Dale, Power_W=100mW, Supplier Part Number 1=541-1.00KHCT-ND, TempCo="100 ppm/C", Tolerance_%=1%, Value2=0.1W, Value_Code=1k00, ValueDisplayed=1.00k
R19: library part CMP-0022556-4, "RES, 69.8 k, 1%, 0.1 W, AEC-Q200 Grade 0, 0603", Manufacturer=Vishay-Dale, PartNumber=CRCW060369K8FKEA, Power_W=100mW, Supplier Part Number 1=541-69.8KHCT-ND, TempCo="100 ppm/C", Tolerance_%=1%, Value2=0.1W, Value_Code=69k8, ValueDisplayed=69.8k
R20: library part CMP-0022260-4, "RES, 28.0 k, 1%, 0.1 W, AEC-Q200 Grade 0, 0603", Manufacturer=Vishay-Dale, Power_W=100mW, Supplier Part Number 1=541-28.0KHCT-ND, TempCo="100 ppm/C", Tolerance_%=1%, Value2=0.1W, Value_Code=28k0, ValueDisplayed=28.0k
R21: library part CMP-0022252-4, "RES, 274 k, 1%, 0.1 W, AEC-Q200 Grade 0, 0603", Manufacturer=Vishay-Dale, Power_W=100mW, Supplier Part Number 1=541-274KHCT-ND, TempCo="100 ppm/C", Tolerance_%=1%, Value2=0.1W, Value_Code=274k
R22: library part CMP-0022447-4, "RES, 49.9 k, 1%, 0.1 W, AEC-Q200 Grade 0, 0603", Manufacturer=Vishay-Dale, Power_W=100mW, Supplier Part Number 1=541-49.9KHCT-ND, TempCo="100 ppm/C", Tolerance_%=1%, Value2=0.1W, Value_Code=49k9, ValueDisplayed=49.9k
R23: library part CMP-0021376-3, "RES, 63.4, 1%, 0.125 W, AEC-Q200 Grade 0, 0805", Manufacturer=Vishay-Dale, PartNumber=CRCW080563R4FKEA, Power_W=125mW, Supplier Part Number 1=541-63.4CCT-ND, TempCo="100 ppm/C", Tolerance_%=1%, Value2=0.125W, Value_Code=63R4, ValueDisplayed=63.4
R24 R32 R33: library part CMP-0021998-4, "RES, 10.0 k, 1%, 0.1 W, AEC-Q200 Grade 0, 0603", Manufacturer=Vishay-Dale, Power_W=100mW, Supplier Part Number 1=541-10.0KHCT-ND, TempCo="100 ppm/C", Tolerance_%=1%, Value2=0.1W, Value_Code=10k0, ValueDisplayed=10.0k
R25: library part CMP-0022237-4, "RES, 24.9 k, 1%, 0.1 W, AEC-Q200 Grade 0, 0603", Manufacturer=Vishay-Dale, PartNumber=CRCW060324K9FKEA, Power_W=100mW, Supplier Part Number 1=541-24.9KHCT-ND, TempCo="100 ppm/C", Tolerance_%=1%, Value2=0.1W, Value_Code=24k9, ValueDisplayed=24.9k
R26: library part CMP-0025874-4, "RES, 0, 5%, 0.1 W, AEC-Q200 Grade 0, 0603", Manufacturer=Panasonic, PartNumber=ERJ-3GEY0R00V, Power_W=100mW, Supplier Part Number 1=P0.0GCT-ND, TempCo="600 ppm/C", Tolerance_%=5%, Value2=0.1W, Value_Code=0000, ValueDisplayed=0
R27: library part CMP-0022126-4, "RES, 1.50 k, 1%, 0.1 W, AEC-Q200 Grade 0, 0603", Manufacturer=Vishay-Dale, Power_W=100mW, Supplier Part Number 1=541-1.50KHCT-ND, TempCo="100 ppm/C", Tolerance_%=1%, Value2=0.1W, Value_Code=1k50, ValueDisplayed=1.50k
R28: library part CMP-0021998-4, "RES, 10.0 k, 1%, 0.1 W, AEC-Q200 Grade 0, 0603", Manufacturer=Vishay-Dale, PartNumber=CRCW060310K0FKEA, Power_W=100mW, Supplier Part Number 1=541-10.0KHCT-ND, TempCo="100 ppm/C", Tolerance_%=1%, Value2=0.1W, Value_Code=10k0, ValueDisplayed=10.0k
R29: library part CMP-0022558-4, "RES, 6.04 k, 1%, 0.1 W, AEC-Q200 Grade 0, 0603", Manufacturer=Vishay-Dale, Power_W=100mW, Supplier Part Number 1=541-6.04KHCT-ND, TempCo="100 ppm/C", Tolerance_%=1%, Value2=0.1W, Value_Code=6k04, ValueDisplayed=6.04k
R30: library part CMP-0022268-4, "RES, 2.00 k, 1%, 0.1 W, AEC-Q200 Grade 0, 0603", Manufacturer=Vishay-Dale, PartNumber=CRCW06032K00FKEA, Power_W=100mW, Supplier Part Number 1=541-2.00KHCT-ND, TempCo="100 ppm/C", Tolerance_%=1%, Value2=0.1W, Value_Code=2k00, ValueDisplayed=2.00k
R31: library part CMP-0022458-4, "RES, 4.99 k, 1%, 0.1 W, AEC-Q200 Grade 0, 0603", Manufacturer=Vishay-Dale, Power_W=100mW, Supplier Part Number 1=541-4.99KHCT-ND, TempCo="100 ppm/C", Tolerance_%=1%, Value2=0.1W, Value_Code=4k99, ValueDisplayed=4.99k
R34: library part CMP-0022115-4, "RES, 1.15 k, 1%, 0.1 W, AEC-Q200 Grade 0, 0603", Manufacturer=Vishay-Dale, Power_W=100mW, Supplier Part Number 1=541-1.15KHCT-ND, TempCo="100 ppm/C", Tolerance_%=1%, Value2=0.1W, Value_Code=1k15, ValueDisplayed=1.15k
T1: library part CMP-0030595-1, "Transformer, 350 uH, SMT", Manufacturer="Wurth Elektronik", ValueDisplayed=350uH
T2: library part CMP-0087126-1, "Transformer, SMT Flyback for PoE/PD, 25W, 24V, 1A", Manufacturer=Wurth, PartNumber=750318587
U1: library part CMP-0031315-4, "IEEE 802.3at, High Efficiency, PoE Interface and DC/DC Controller, PWP0020D (HTSSOP-20)", Auxiliary/Local Power Support=Programmable, Auxiliary Power Rails Supported=24V-57V, Manufacturer="Texas Instruments", Operating Temperature Range="-40 to 125 C", PD Power Level=25W, PoE Current Limit(Min)(mA)=850, Rating=Catalog, Switching Frequency="Synchronizable and Programmable"
U2: library part CMP-0006167-3, "Optocoupler, 3.75 kV, 300-600% CTR, SMT", Manufacturer="Sharp Microelectronics", Supplier Part Number 1=425-2093-1-ND, Voltage_Isolation_Vrms=3.75kV
U3: library part CMP-0006166-3, "Optocoupler, 3.75 kV, 80-160% CTR, SMT", Manufacturer=Vishay-Semiconductor, Supplier Part Number 1=TCMT1107CT-ND, Voltage_Isolation_Vrms=3.75kV
U4: library part CMP-0084729-1, "Programmable Shunt Regulator with Optimized Reference Current, DBZ0003A (SOT-23-3)", Alternate Manufacturer="Texas Instruments"

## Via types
v1: diameter 34, hole 16, Top Layer to Bottom Layer, 97 vias
v2: diameter 19.68, hole 7.87, Top Layer to Bottom Layer, tented both sides, 12 vias
v3: diameter 19.68, hole 7.87, Top Layer to Bottom Layer, 3 vias

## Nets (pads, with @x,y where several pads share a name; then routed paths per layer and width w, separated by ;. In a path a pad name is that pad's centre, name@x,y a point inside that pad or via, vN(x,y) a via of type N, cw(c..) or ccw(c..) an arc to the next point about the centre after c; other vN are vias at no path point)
AUX: C7.2 D1.2 L2.1 R16.2 | length 670.2
  Top Layer w15: L2.1@2345,360 2360,375 2360,425 2370,435 2645,435 2675,465 R16.2@2675,732.44
BSP: C1.1 C6.2 J1.9 J1.10 J1.11 J1.12 J2.9 J2.10 J2.11 J2.12
  other v1: 150,990 150,1375
GND: C11.1 C17.2 C18.1 C19.1 C20.1 C21.1 C22.2 C24.1 C33.2 J5.2 J6.2 R34.2 T2.11 T2.12 U2.3 U4.3 | length 330.3
  Top Layer w15: v1(2160,2420) U4.3@2211.69,2420 ; v1(2185,2530) R34.2@2242.44,2530 ; C33.2@2419.53,2275 2420,2274.53 v1(2420,2215)
  Top Layer w25: U2.3@2675,2139.02 J6.2@2675,2300
  other v1: 1330,2175 1410,2175 1665,2175 1583.9,2175.67 1310,2550 1430,2550 2155,2590 2295,2590 1310,2615 1430,2615 1165,2690 1220,2690 1305,2690 1365,2690 1445,2690 1505,2690 1855,2690 1915,2690 2155,2690 2295,2690 2425,2695
NetC1_2: C1.2 R1.2 R2.2 R3.2 R8.1 | length 576.7
  Bottom Layer w15: C1.2@308.74,1265 308.74,1221.1 312.4,1217.44 R8.1@390,1217.44 R3.2@540,1217.44 R2.2@690,1217.44 R1.2@840,1217.44
NetC2_1: C2.1 R4.2 | length 49.9
  Bottom Layer w15: C2.1@840,1047.56 R4.2@840,1097.44
NetC3_1: C3.1 R5.2 | length 49.9
  Bottom Layer w15: C3.1@690,1047.56 R5.2@690,1097.44
NetC4_1: C4.1 R6.2 | length 49.9
  Bottom Layer w15: C4.1@540,1047.56 R6.2@540,1097.44
NetC5_1: C5.1 R7.2 | length 49.9
  Bottom Layer w15: C5.1@390,1047.56 R7.2@390,1097.44
NetC6_1: C6.1 R4.1 R5.1 R6.1 R7.1 | length 580.2
  Bottom Layer w15: C6.1@308.74,1100 308.74,1146.3 315,1152.56 R7.1@390,1152.56 R6.1@540,1152.56 R5.1@690,1152.56 R4.1@840,1152.56
NetC8_1: C8.1 J3.1 L2.2 | length 318.2
  Top Layer w25: C8.1@2425,272.56 L2.2@2425,360
  Top Layer w50: L2.2@2425,360 2585,360 J3.1@2635,310
NetC8_2: C8.2 J3.2 L3.2 | length 322
  Top Layer w25: L3.2@2425,125 C8.2@2425,217.44
  Top Layer w50: L3.2@2425,125 2587.8,125 J3.2@2635,172.2
NetC9_1: C9.1 D2.1 D3.1 D4.1 D5.1 L1.1 | length 511.1
  Top Layer w25: C9.1@1590,250 L1.1@1590,314.53 ; L1.1@1590,320 L1.1@1590,314.53 ; L1.1@1595.47,320 L1.1@1590,314.53
  Top Layer w40: L1.1@1590,320 v1(1590,400)
  Bottom Layer w40: D2.1@1480,141.26 1563.7,141.26 1590,167.56 v1(1590,400)
NetC9_2: C9.2 D6.2 D7.2 D8.2 D9.2 L4.1
NetC11_2: C11.2 C14.1 C15.1 C16.2 L5.2 R11.2 T2.1 T2.2 | length 419.9
  Bottom Layer w60: C11.2@1370,1925 1370,1590 v1(1430,1530)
